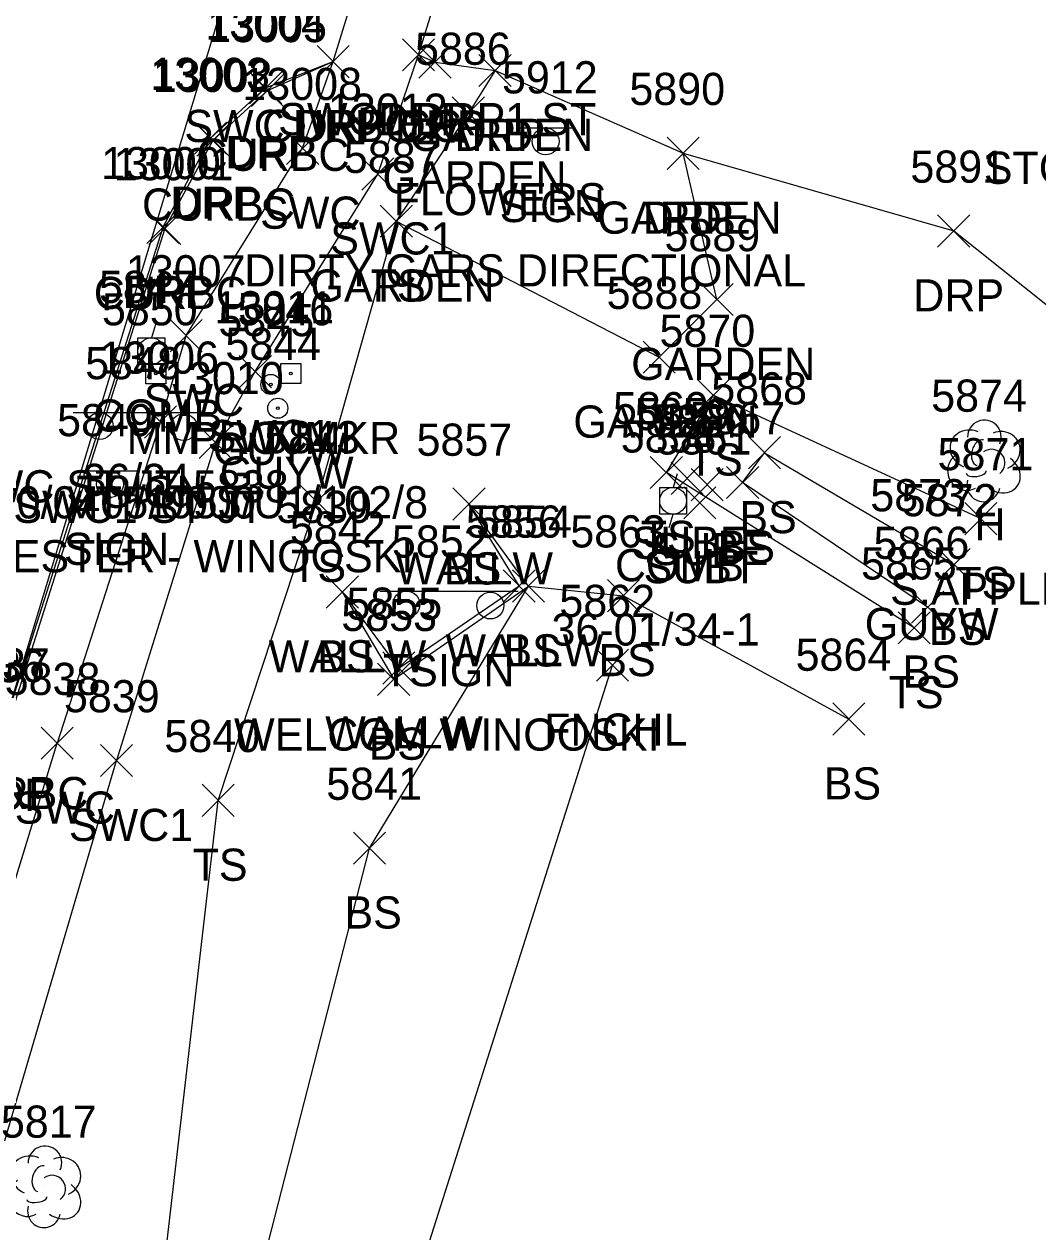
# Model space of a CAD drawing. Extents: x 1462089 to 1464015, y 730534 to 736144.
# Drawn here: x 1462403.3 to 1462466.3, y 730610.6 to 730685.7 of the extents above; entities that cross this region are included whole.
import ezdxf

# ---------------------------------------------------------------- set-up
doc = ezdxf.new("R2010")
doc.units = 0
for name, color, linetype in [('L_A', 7, 'Continuous'), ('L_C', 7, 'Continuous'), ('L_I', 7, 'Continuous'), ('L_TIC', 7, 'Continuous'), ('LAPB', 7, 'Continuous'), ('LELB', 7, 'Continuous'), ('LFNC', 7, 'Continuous'), ('LTD', 7, 'Continuous'), ('LW', 7, 'Continuous'), ('P_A', 7, 'Continuous'), ('P_I', 7, 'Continuous'), ('PET', 7, 'Continuous'), ('R_A', 7, 'Continuous'), ('R_C', 7, 'Continuous'), ('R_I', 7, 'Continuous'), ('R_TIC', 7, 'Continuous'), ('RC', 7, 'Continuous'), ('RDP', 7, 'Continuous'), ('RSW', 7, 'Continuous'), ('S_A', 7, 'Continuous'), ('S_C', 7, 'Continuous'), ('S_I', 7, 'Continuous'), ('SRM', 7, 'Continuous'), ('SSGN', 7, 'Continuous'), ('U_A', 7, 'Continuous'), ('U_C', 7, 'Continuous'), ('U_I', 7, 'Continuous'), ('U_TIC', 7, 'Continuous'), ('UP', 7, 'Continuous'), ('UPGW', 7, 'Continuous')]:
    doc.layers.add(name, color=color, linetype=linetype)

msp = doc.modelspace()

# ---------------------------------------------------------------- linework, layer by layer
at = {"layer": 'L_TIC'}
for points in [[(1462431.575, 730681.804), (1462433.575, 730683.804)], [(1462433.575, 730681.804), (1462431.575, 730683.804)], [(1462429.918, 730679.158), (1462431.918, 730681.158)], [(1462431.918, 730679.158), (1462429.918, 730681.158)], [(1462443.274, 730676.66), (1462445.274, 730678.66)], [(1462445.274, 730676.66), (1462443.274, 730678.66)], [(1462425.438, 730672.437), (1462427.438, 730674.437)], [(1462427.438, 730672.437), (1462425.438, 730674.437)], [(1462425.438, 730672.437), (1462427.438, 730674.437)], [(1462427.438, 730672.437), (1462425.438, 730674.437)], [(1462445.373, 730667.571), (1462447.373, 730669.571)], [(1462447.373, 730667.571), (1462445.373, 730669.571)], [(1462441.774, 730663.983), (1462443.774, 730665.983)], [(1462443.774, 730663.983), (1462441.774, 730665.983)], [(1462445.148, 730661.629), (1462447.148, 730663.629)], [(1462447.148, 730661.629), (1462445.148, 730663.629)], [(1462448.324, 730658.047), (1462450.324, 730660.047)], [(1462450.324, 730658.047), (1462448.324, 730660.047)], [(1462442.225, 730656.817), (1462444.225, 730658.817)], [(1462444.225, 730656.817), (1462442.225, 730658.817)], [(1462446.968, 730656.202), (1462448.968, 730658.202)], [(1462448.968, 730656.202), (1462446.968, 730658.202)], [(1462420.493, 730655.015), (1462422.493, 730657.015)], [(1462422.493, 730655.015), (1462420.493, 730657.015)], [(1462429.958, 730654.86), (1462431.958, 730656.86)], [(1462431.958, 730654.86), (1462429.958, 730656.86)], [(1462429.958, 730654.86), (1462431.958, 730656.86)], [(1462431.958, 730654.86), (1462429.958, 730656.86)], [(1462461.777, 730653.955), (1462463.777, 730655.955)], [(1462463.777, 730653.955), (1462461.777, 730655.955)], [(1462460.107, 730651.101), (1462462.107, 730653.101)], [(1462462.107, 730651.101), (1462460.107, 730653.101)], [(1462422.085, 730649.397), (1462424.085, 730651.397)], [(1462424.085, 730649.397), (1462422.085, 730651.397)], [(1462422.085, 730649.397), (1462424.085, 730651.397)], [(1462424.085, 730649.397), (1462422.085, 730651.397)], [(1462433.08, 730649.771), (1462435.08, 730651.771)], [(1462435.08, 730649.771), (1462433.08, 730651.771)], [(1462433.658, 730649.764), (1462435.658, 730651.764)], [(1462435.658, 730649.764), (1462433.658, 730651.764)], [(1462433.658, 730649.764), (1462435.658, 730651.764)], [(1462435.658, 730649.764), (1462433.658, 730651.764)], [(1462439.56, 730649.16), (1462441.56, 730651.16)], [(1462441.56, 730649.16), (1462439.56, 730651.16)], [(1462458.465, 730648.45), (1462460.465, 730650.45)], [(1462460.465, 730648.45), (1462458.465, 730650.45)], [(1462457.63, 730647.169), (1462459.63, 730649.169)], [(1462459.63, 730647.169), (1462457.63, 730649.169)], [(1462438.882, 730644.841), (1462440.882, 730646.841)], [(1462440.882, 730644.841), (1462438.882, 730646.841)], [(1462425.281, 730643.966), (1462427.281, 730645.966)], [(1462427.281, 730643.966), (1462425.281, 730645.966)], [(1462425.602, 730644.667), (1462427.602, 730646.667)], [(1462427.602, 730644.667), (1462425.602, 730646.667)], [(1462453.565, 730641.497), (1462455.565, 730643.497)], [(1462455.565, 730641.497), (1462453.565, 730643.497)], [(1462414.369, 730636.443), (1462416.369, 730638.443)], [(1462416.369, 730636.443), (1462414.369, 730638.443)], [(1462423.777, 730633.476), (1462425.777, 730635.476)], [(1462425.777, 730633.476), (1462423.777, 730635.476)]]:
    msp.add_lwpolyline(points, dxfattribs=at)
at = {"layer": 'LAPB'}
msp.add_lwpolyline([(1462432.575, 730682.804), (1462430.918, 730680.158), (1462426.438, 730673.437), (1462442.774, 730664.983), (1462446.373, 730668.571), (1462444.274, 730677.66)], dxfattribs=at)
at = {"layer": 'LELB'}
for points in [[(1462384.18, 730547.242), (1462410.14, 730592.357), (1462415.369, 730637.443), (1462421.493, 730656.015), (1462426.438, 730673.437)], [(1462458.63, 730648.169), (1462443.225, 730657.817), (1462446.148, 730662.629), (1462462.777, 730654.955)], [(1462459.465, 730649.45), (1462447.968, 730657.202), (1462449.324, 730659.047), (1462461.107, 730652.101)], [(1462423.085, 730650.397), (1462426.281, 730644.966), (1462434.658, 730650.764), (1462430.958, 730655.86)], [(1462394.536, 730544.056), (1462413.831, 730591.827), (1462424.777, 730634.476), (1462434.658, 730650.764), (1462440.56, 730650.16), (1462454.565, 730642.497)]]:
    msp.add_lwpolyline(points, dxfattribs=at)
at = {"layer": 'LFNC'}
msp.add_lwpolyline([(1462405.433, 730538.655), (1462421.846, 730589.074), (1462439.882, 730645.841)], dxfattribs=at)
at = {"layer": 'LTD'}
for p, q in [((1462462.947, 730658.596), (1462462.947, 730658.596)), ((1462462.947, 730658.596), (1462462.947, 730658.596)), ((1462404.554, 730613.475), (1462404.554, 730613.475)), ((1462404.554, 730613.475), (1462404.554, 730613.475))]:
    msp.add_line(p, q, dxfattribs=at)
for centre in [(1462462.994, 730660.03), (1462404.601, 730614.909)]:
    msp.add_arc(centre, 1.047, 335.52715, 180.95627, dxfattribs=at)
for centre, major_axis, ratio, start_param, end_param in [((1462462.155, 730659.263), (1.21, -0.512), 0.895232, 1.570796, 4.712389), ((1462463.988, 730659.18), (-1.141, -0.483), 0.949671, 1.570796, 4.712389), ((1462462.738, 730659.055), (-0.208, -0.792), 0.645439, 3.141593, 6.283185), ((1462461.864, 730657.888), (0.584, -1.042), 0.959034, 3.141593, 6.283185), ((1462463.447, 730658.43), (-0.5, 0.667), 0.989748, 3.141593, 6.283185), ((1462463.947, 730657.763), (-1.09, 0.792), 0.841452, 1.570796, 4.712389), ((1462462.947, 730657.096), (0.265, 1.061), 0.942809, 1.570796, 4.712389), ((1462462.489, 730657.846), (-0.625, -0.083), 0.423636, 0, 3.141593), ((1462403.762, 730614.141), (1.21, -0.512), 0.895232, 1.570796, 4.712389), ((1462405.596, 730614.058), (-1.141, -0.483), 0.949671, 1.570796, 4.712389), ((1462404.346, 730613.933), (-0.208, -0.792), 0.645439, 3.141593, 6.283185), ((1462403.471, 730612.766), (0.584, -1.042), 0.959034, 3.141593, 6.283185), ((1462405.054, 730613.308), (-0.5, 0.667), 0.989748, 3.141593, 6.283185), ((1462405.554, 730612.642), (-1.09, 0.792), 0.841452, 1.570796, 4.712389), ((1462404.554, 730611.975), (0.265, 1.061), 0.942809, 1.570796, 4.712389), ((1462404.096, 730612.725), (-0.625, -0.083), 0.423636, 0, 3.141593)]:
    msp.add_ellipse(centre, major_axis=major_axis, ratio=ratio, start_param=start_param, end_param=end_param, dxfattribs=at)
at = {"layer": 'LW'}
msp.add_lwpolyline([(1462423.085, 730650.397), (1462426.602, 730645.667), (1462434.08, 730650.771), (1462430.958, 730655.86)], dxfattribs=at)
at = {"layer": 'PET'}
msp.add_lwpolyline([(1462373.445, 730550.573), (1462388.309, 730598.891), (1462401.963, 730641.783), (1462433.168, 730744.632), (1462438.196, 730760.147), (1462452.976, 730810.554), (1462463.625, 730846.159), (1462471.864, 730873.588), (1462478.576, 730896.599), (1462485.477, 730919.066), (1462495.517, 730952.686), (1462508.095, 730994.119), (1462517.419, 731025.054), (1462526.796, 731054.959), (1462537.856, 731087.551), (1462549.797, 731117.253), (1462553.734, 731129.646)], dxfattribs=at)
at = {"layer": 'R_TIC'}
for points in [[(1462421.516, 730682.357), (1462423.516, 730684.357)], [(1462423.516, 730682.357), (1462421.516, 730684.357)], [(1462421.516, 730682.357), (1462423.516, 730684.357)], [(1462423.516, 730682.357), (1462421.516, 730684.357)], [(1462421.516, 730682.357), (1462423.516, 730684.357)], [(1462423.516, 730682.357), (1462421.516, 730684.357)], [(1462426.816, 730682.782), (1462428.816, 730684.782)], [(1462428.816, 730682.782), (1462426.816, 730684.782)], [(1462426.816, 730682.782), (1462428.816, 730684.782)], [(1462428.816, 730682.782), (1462426.816, 730684.782)], [(1462427.849, 730682.327), (1462429.849, 730684.327)], [(1462429.849, 730682.327), (1462427.849, 730684.327)], [(1462431.575, 730681.804), (1462433.575, 730683.804)], [(1462433.575, 730681.804), (1462431.575, 730683.804)], [(1462417.315, 730680.724), (1462419.315, 730682.724)], [(1462419.315, 730680.724), (1462417.315, 730682.724)], [(1462417.438, 730680.566), (1462419.438, 730682.566)], [(1462419.438, 730680.566), (1462417.438, 730682.566)], [(1462413.893, 730677.594), (1462415.893, 730679.594)], [(1462415.893, 730677.594), (1462413.893, 730679.594)], [(1462414.05, 730677.47), (1462416.05, 730679.47)], [(1462416.05, 730677.47), (1462414.05, 730679.47)], [(1462419.616, 730676.969), (1462421.616, 730678.969)], [(1462421.616, 730676.969), (1462419.616, 730678.969)], [(1462443.274, 730676.66), (1462445.274, 730678.66)], [(1462445.274, 730676.66), (1462443.274, 730678.66)], [(1462424.293, 730675.369), (1462426.293, 730677.369)], [(1462426.293, 730675.369), (1462424.293, 730677.369)], [(1462410.925, 730672.051), (1462412.925, 730674.051)], [(1462412.925, 730672.051), (1462410.925, 730674.051)], [(1462411.054, 730671.981), (1462413.054, 730673.981)], [(1462413.054, 730671.981), (1462411.054, 730673.981)], [(1462460.086, 730671.83), (1462462.086, 730673.83)], [(1462462.086, 730671.83), (1462460.086, 730673.83)], [(1462412.375, 730665.326), (1462414.375, 730667.326)], [(1462414.375, 730665.326), (1462412.375, 730667.326)], [(1462416.674, 730663.088), (1462418.674, 730665.088)], [(1462418.674, 730663.088), (1462416.674, 730665.088)], [(1462410.78, 730659.96), (1462412.78, 730661.96)], [(1462412.78, 730659.96), (1462410.78, 730661.96)], [(1462414.196, 730658.689), (1462416.196, 730660.689)], [(1462416.196, 730658.689), (1462414.196, 730660.689)], [(1462404.356, 730639.993), (1462406.356, 730641.993)], [(1462406.356, 730639.993), (1462404.356, 730641.993)], [(1462408.048, 730638.916), (1462410.048, 730640.916)], [(1462410.048, 730638.916), (1462408.048, 730640.916)]]:
    msp.add_lwpolyline(points, dxfattribs=at)
at = {"layer": 'RC'}
for points in [[(1462412.054, 730672.981), (1462415.05, 730678.47), (1462418.438, 730681.566), (1462422.516, 730683.357)], [(1462412.054, 730672.981), (1462402.208, 730641.896)]]:
    msp.add_lwpolyline(points, dxfattribs=at)
at = {"layer": 'RDP'}
for points in [[(1462427.816, 730683.782), (1462428.849, 730683.327)], [(1462411.925, 730673.051), (1462414.893, 730678.594), (1462418.315, 730681.724), (1462422.516, 730683.357)], [(1462428.849, 730683.327), (1462432.575, 730682.804)], [(1462432.575, 730682.804), (1462444.274, 730677.66), (1462461.086, 730672.83), (1462469.882, 730665.836)], [(1462411.925, 730673.051), (1462401.963, 730641.783)]]:
    msp.add_lwpolyline(points, dxfattribs=at)
at = {"layer": 'RSW'}
for points in [[(1462411.78, 730660.96), (1462413.375, 730666.326), (1462420.616, 730677.969), (1462422.516, 730683.357), (1462438.143, 730733.978), (1462442.863, 730748.711), (1462450.22, 730769.258), (1462462.602, 730809.869), (1462469.677, 730832.394), (1462475.297, 730861.235), (1462478.395, 730877.187), (1462489.057, 730911.55)], [(1462415.196, 730659.689), (1462417.674, 730664.088), (1462425.293, 730676.369), (1462427.816, 730683.782), (1462442.002, 730729.636), (1462442.779, 730732.808), (1462445.728, 730742.244), (1462455.055, 730768.12), (1462467.301, 730808.318), (1462474.256, 730831.161), (1462480.008, 730860.315), (1462483.021, 730875.428), (1462493.434, 730909.857)], [(1462411.78, 730660.96), (1462405.356, 730640.993)], [(1462415.196, 730659.689), (1462409.048, 730639.916)], [(1462376.574, 730549.426), (1462392.14, 730597.919), (1462405.356, 730640.993)], [(1462380.351, 730548.047), (1462396.125, 730596.001), (1462409.048, 730639.916)]]:
    msp.add_lwpolyline(points, dxfattribs=at)
at = {"layer": 'SRM'}
for points in [[(1462410.865, 730664.589), (1462412.115, 730664.589), (1462412.115, 730663.339), (1462410.865, 730663.339)], [(1462419.259, 730664.593), (1462420.509, 730664.593), (1462420.509, 730663.343), (1462419.259, 730663.343)]]:
    msp.add_lwpolyline(points, close=True, dxfattribs=at)
for centre in [(1462411.49, 730663.964), (1462419.884, 730663.968)]:
    msp.add_circle(centre, 0.0833, dxfattribs=at)
at = {"layer": 'SSGN'}
for p, q in [((1462434.073, 730679.235), (1462437.406, 730679.235)), ((1462435.72, 730678.402), (1462435.72, 730678.402)), ((1462406.347, 730661.54), (1462414.944, 730661.54)), ((1462410.369, 730660.637), (1462410.369, 730660.637)), ((1462406.996, 730657.928), (1462410.329, 730657.928)), ((1462408.643, 730657.095), (1462408.643, 730657.095)), ((1462425.409, 730650.453), (1462434.006, 730650.453)), ((1462429.431, 730649.55), (1462429.431, 730649.55))]:
    msp.add_line(p, q, dxfattribs=at)
for centre in [(1462435.72, 730678.402), (1462408.008, 730660.707), (1462413.223, 730660.637), (1462408.643, 730657.095), (1462427.07, 730649.62), (1462432.285, 730649.55)]:
    msp.add_circle(centre, 0.833, dxfattribs=at)
at = {"layer": 'U_TIC'}
for points in [[(1462443.523, 730656.455), (1462445.523, 730658.455)], [(1462445.523, 730656.455), (1462443.523, 730658.455)], [(1462444.765, 730656.063), (1462446.765, 730658.063)], [(1462446.765, 730656.063), (1462444.765, 730658.063)], [(1462444.309, 730654.937), (1462446.309, 730656.937)], [(1462446.309, 730654.937), (1462444.309, 730656.937)]]:
    msp.add_lwpolyline(points, dxfattribs=at)
at = {"layer": 'UP'}
for p, q in [((1462411.465, 730667.026), (1462411.215, 730666.193)), ((1462410.382, 730664.526), (1462410.382, 730666.193)), ((1462410.382, 730666.193), (1462412.049, 730666.193)), ((1462412.049, 730666.193), (1462412.049, 730664.526)), ((1462411.215, 730665.36), (1462411.215, 730665.36)), ((1462412.049, 730664.526), (1462410.382, 730664.526)), ((1462410.965, 730663.693), (1462411.215, 730664.526)), ((1462443.896, 730657.728), (1462443.646, 730656.894)), ((1462442.813, 730655.228), (1462442.813, 730656.894)), ((1462442.813, 730656.894), (1462444.48, 730656.894)), ((1462444.48, 730656.894), (1462444.48, 730655.228)), ((1462443.646, 730656.061), (1462443.646, 730656.061)), ((1462444.48, 730655.228), (1462442.813, 730655.228)), ((1462443.396, 730654.394), (1462443.646, 730655.228))]:
    msp.add_line(p, q, dxfattribs=at)
for centre in [(1462411.215, 730665.36), (1462443.646, 730656.061)]:
    msp.add_circle(centre, 0.833, dxfattribs=at)
at = {"layer": 'UPGW'}
for centre, radius in [((1462418.645, 730663.292), 0.625), ((1462418.645, 730663.292), 0.0833), ((1462419.074, 730661.812), 0.625), ((1462419.074, 730661.812), 0.0833), ((1462459.163, 730652.406), 0.625), ((1462459.163, 730652.406), 0.0833)]:
    msp.add_circle(centre, radius, dxfattribs=at)

# ---------------------------------------------------------------- texts
at = {"layer": 'L_A'}
for s, p in [('GARDEN', (1462427.244, 730677.804)), ('GARDEN', (1462425.587, 730675.158)), ('GARDEN', (1462438.943, 730672.66)), ('GARDEN', (1462421.108, 730668.437)), ('TS', (1462424.848, 730668.437)), ('GARDEN', (1462441.042, 730663.571)), ('GARDEN', (1462437.443, 730659.983)), ('TS', (1462444.557, 730657.629)), ('BS', (1462447.765, 730654.047)), ('H', (1462462.38, 730653.596)), ('TS', (1462441.635, 730652.817)), ('BS', (1462446.409, 730652.202)), ('TS', (1462419.903, 730651.015)), ('WALLW', (1462426.375, 730650.86)), ('BS', (1462429.399, 730650.86)), ('TS', (1462461.187, 730649.955)), ('BS', (1462459.548, 730647.101)), ('WALLW', (1462429.497, 730645.771)), ('BS', (1462433.099, 730645.764)), ('BS', (1462433.099, 730645.764)), ('WALLW', (1462418.502, 730645.397)), ('BS', (1462421.526, 730645.397)), ('BS', (1462439.001, 730645.16)), ('BS', (1462457.906, 730644.45)), ('TS', (1462457.039, 730643.169)), ('WALLW', (1462422.019, 730640.667)), ('FNCHL', (1462435.63, 730640.841)), ('BS', (1462424.722, 730639.966)), ('BS', (1462453.006, 730637.497)), ('TS', (1462413.778, 730632.443)), ('BS', (1462423.218, 730629.476))]:
    msp.add_text(s, height=2, dxfattribs=at).set_placement(p)
at = {"layer": 'L_C'}
msp.add_text('S.APPLE', height=2, dxfattribs=at).set_placement((1462457.136, 730649.596))
at = {"layer": 'L_I'}
for s, p in [('5886', (1462427.603, 730683.158)), ('5890', (1462440.927, 730680.66)), ('5887', (1462423.178, 730676.437)), ('5887', (1462423.178, 730676.437)), ('5889', (1462443.106, 730671.571)), ('5888', (1462439.514, 730667.983)), ('5870', (1462442.801, 730665.629)), ('5868', (1462446.017, 730662.047)), ('5874', (1462459.687, 730661.596)), ('5869', (1462439.911, 730660.817)), ('5867', (1462444.661, 730660.202)), ('5843', (1462418.233, 730659.015)), ('5857', (1462427.698, 730658.86)), ('5857', (1462427.698, 730658.86)), ('5871', (1462460.084, 730657.955)), ('5872', (1462457.847, 730655.101)), ('5856', (1462430.765, 730653.771)), ('5854', (1462431.399, 730653.764)), ('5854', (1462431.399, 730653.764)), ('5842', (1462419.825, 730653.397)), ('5842', (1462419.825, 730653.397)), ('5863', (1462437.253, 730653.16)), ('5866', (1462456.103, 730652.45)), ('5865', (1462455.323, 730651.169)), ('5855', (1462423.342, 730648.667)), ('5862', (1462436.575, 730648.841)), ('5853', (1462423.021, 730647.966)), ('5864', (1462451.258, 730645.497)), ('5840', (1462412.022, 730640.443)), ('5841', (1462422.085, 730637.476)), ('5817', (1462401.861, 730616.475))]:
    msp.add_text(s, height=2, dxfattribs=at).set_placement(p)
at = {"layer": 'P_A'}
msp.add_text('RDP', height=2, dxfattribs=at).set_placement((1462399.451, 730636.783))
at = {"layer": 'P_I'}
msp.add_text('5836', height=2, dxfattribs=at).set_placement((1462398.648, 730644.783))
at = {"layer": 'R_A'}
for s, p in [('SWC1 DRP1 ST', (1462419.1, 730678.782)), ('DRP', (1462425.304, 730678.782)), ('SWC DRP CC', (1462413.264, 730678.357)), ('CURBC', (1462418.099, 730678.357)), ('DRP', (1462420.004, 730678.357)), ('DRP', (1462426.338, 730678.327)), ('DRP', (1462430.063, 730677.804)), ('CURBC', (1462414.021, 730676.566)), ('DRP', (1462415.803, 730676.724)), ('CURBC', (1462410.633, 730673.47)), ('DRP', (1462412.381, 730673.594)), ('SWC', (1462417.978, 730672.969)), ('DRP', (1462441.762, 730672.66)), ('SWC1', (1462422.333, 730671.369)), ('CURBC', (1462407.637, 730667.981)), ('DRP', (1462409.413, 730668.051)), ('DRP', (1462458.574, 730667.83)), ('SWC', (1462410.738, 730661.326)), ('SWC1', (1462414.714, 730659.088)), ('SWC ST JT 5838', (1462398.946, 730655.96)), ('SWC1 ST JT 5839', (1462402.637, 730654.689)), ('CURBC', (1462397.791, 730636.896)), ('SWC', (1462402.719, 730635.993)), ('SWC1', (1462406.088, 730634.916))]:
    msp.add_text(s, height=2, dxfattribs=at).set_placement(p)
at = {"layer": 'R_C'}
msp.add_text('FLOWERS', height=2, dxfattribs=at).set_placement((1462426.276, 730673.804))
at = {"layer": 'R_I'}
for s, p in [('13004', (1462414.567, 730684.724)), ('13005', (1462414.69, 730684.566)), ('13003', (1462411.145, 730681.594)), ('13002', (1462411.303, 730681.47)), ('13008', (1462416.868, 730680.969)), ('5890', (1462440.927, 730680.66)), ('13012', (1462422.191, 730679.369)), ('13000', (1462408.091, 730676.051)), ('13001', (1462408.873, 730675.981)), ('5891', (1462458.393, 730675.83)), ('13007', (1462409.628, 730669.326)), ('13011', (1462415.139, 730667.088)), ('13006', (1462407.977, 730663.96)), ('13010', (1462412.007, 730662.689)), ('5837', (1462398.949, 730644.896)), ('5838', (1462402.097, 730643.993)), ('5839', (1462405.781, 730642.916))]:
    msp.add_text(s, height=2, dxfattribs=at).set_placement(p)
at = {"layer": 'S_A'}
for s, p in [('SIGN', (1462432.858, 730673.381)), ('MM', (1462409.679, 730658.964)), ('PROJMKR', (1462413.609, 730658.968)), ('TSIGN', (1462406.545, 730655.619)), ('SIGN', (1462405.781, 730652.075)), ('TSIGN', (1462425.607, 730644.532))]:
    msp.add_text(s, height=2, dxfattribs=at).set_placement(p)
at = {"layer": 'S_C'}
for s, p in [('DIRTY CARS DIRECTIONAL', (1462416.992, 730669.381)), ('0070/0405/0000', (1462398.38, 730654.964)), ('VT /1953/U1/102/8', (1462405.964, 730654.968)), ('T/L COLCHESTER - WINOOSKI', (1462388.569, 730651.619)), ('WELCOM WINOOSKI', (1462416.355, 730640.532))]:
    msp.add_text(s, height=2, dxfattribs=at).set_placement(p)
at = {"layer": 'S_I'}
for s, p in [('5912', (1462433.008, 730681.381)), ('5850', (1462408.143, 730666.964)), ('5846', (1462416.569, 730666.968)), ('5848', (1462407.104, 730663.619)), ('5849', (1462405.356, 730660.075)), ('5852', (1462426.166, 730652.532))]:
    msp.add_text(s, height=2, dxfattribs=at).set_placement(p)
at = {"layer": 'U_A'}
for s, p in [('COMB', (1462407.601, 730660.36)), ('GUYW', (1462415.038, 730658.292)), ('GUYW', (1462415.468, 730656.812)), ('SUBE', (1462441.058, 730652.455)), ('SUBE', (1462442.301, 730652.063)), ('COMB', (1462440.032, 730651.061)), ('SUBT', (1462441.805, 730650.937)), ('GUYW', (1462455.557, 730647.406))]:
    msp.add_text(s, height=2, dxfattribs=at).set_placement(p)
at = {"layer": 'U_C'}
for s, p in [('STORM & SEWER', (1462462.959, 730675.76)), ('36/34', (1462406.932, 730656.36)), ('36-01/34-1', (1462436.087, 730647.061))]:
    msp.add_text(s, height=2, dxfattribs=at).set_placement(p)
at = {"layer": 'U_I'}
for s, p in [('5847', (1462407.955, 730668.36)), ('5845', (1462415.385, 730666.292)), ('5844', (1462415.815, 730664.812)), ('5859', (1462441.255, 730660.455)), ('5860', (1462442.371, 730660.063)), ('5858', (1462440.386, 730659.061)), ('5861', (1462442.569, 730658.937)), ('5873', (1462455.904, 730655.406))]:
    msp.add_text(s, height=2, dxfattribs=at).set_placement(p)

doc.saveas('drawing.dxf')
